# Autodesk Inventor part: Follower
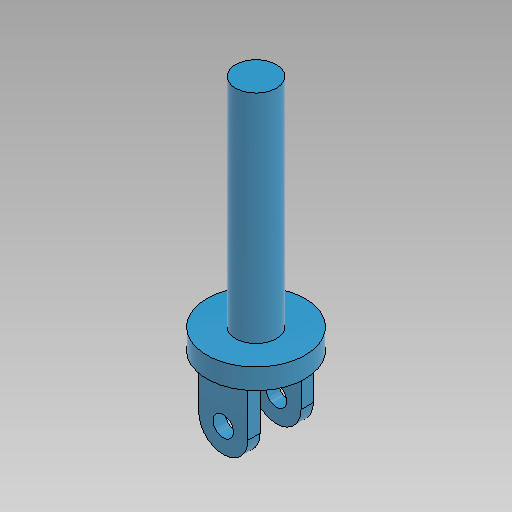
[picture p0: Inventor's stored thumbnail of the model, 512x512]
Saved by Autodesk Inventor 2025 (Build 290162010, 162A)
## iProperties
Created: 2024-10
Part Number: Follower
Material: Generic
Document SubType Name: Modeling
Designer: Dennis
Mass: 7.51004 g
Surface Area: 39.4981 cm^2
Volume: 7.51004 cm^3
Density: 1 g/cm^3
Appearance: Sky Blue Dark
Author: Dennis
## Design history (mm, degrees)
sketch "Sketch1"
  geometry: L1 (-6, 0)-(-6, 12); L2 (-6, 12)-(6, 12); L3 (6, 0)-(6, 12); C1 r 2.5 at (0, 0); A1 r 6 centre (0, 0) between (-6, 0) and (6, 0); 1 further point
  constraints: 6 end point, 2 centre point, 2 coincident, 2 point on circle, 2 tangent, 2 vertical, 1 perpendicular
  dimensions: "d0" = 12 distance of L3.start L2.end; "d1" = 6 radius of A1; "d2" = 5 diameter of C1
extrude "Extrusion1" new body sketch "Sketch1" stored distance "d3" = 16; taper "d4" = 0 deg
sketch "Sketch2"
  geometry: L1 (-6, 12)-(6, 12) reference; L2 (0, 12)-(12, 12); L3 (12, 12)-(12, 17); L4 (12, 17)-(5, 17); L5 (5, 17)-(5, 70); L6 (5, 70)-(0, 70); L7 (0, 70)-(0, 12); 1 further point
  constraints: 12 end point, 5 perpendicular, 1 horizontal, 1 midpoint
  dimensions: "d6" = 5 distance of L2.end L3.end; "d7" = 24 diameter of L3 L7; "d8" = 10 diameter of L5 L7; "d12" = 53 distance between parallel lines of L6 L4
revolve "Revolution1" sketch "Sketch2" stored, may be unused: angle "d9" = 90 deg
sketch "Sketch3"
  geometry: L1 (-12, 12)-(12, 12) reference; L2 (12, 12)-(-12, 12); L3 (-12, 12)-(-12, -9.522); L4 (-12, -9.522)-(12, -9.522); L5 (12, -9.522)-(12, 12); 1 further point
  constraints: 8 end point, 2 parallel, 1 horizontal, 1 perpendicular
extrude "Extrusion2" cut sketch "Sketch3" stored distance "d10" = 10; taper "d11" = 0 deg
body "Solid1"
